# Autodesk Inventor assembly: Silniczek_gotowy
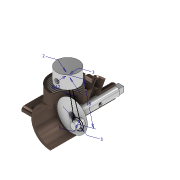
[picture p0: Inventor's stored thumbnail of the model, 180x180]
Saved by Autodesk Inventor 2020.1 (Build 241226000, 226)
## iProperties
Manager: www.cadconsulting.pl
Company: Fabian Stasiak CAD Consulting
Created: 2019-06
Part Number: Silniczek_gotowy
Document SubType Name: Assembly
Designer: F.Stasiak
Author: F.Stasiak
Subject: Zbiór ćwiczeń. Autodesk Inventor 2020. Kurs podstawowy
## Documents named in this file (5)
- C:\2020_Kurs_podstawowy\R6 Zespoły\Wiązania\Silniczek\Silniczek_gotowy.iam
- C:\2020_Kurs_podstawowy\R6 Zespoły\Wiązania\Silniczek\Korpus_234.ipt
- C:\2020_Kurs_podstawowy\R6 Zespoły\Wiązania\Silniczek\Wałek_234.ipt
- C:\2020_Kurs_podstawowy\R6 Zespoły\Wiązania\Silniczek\Tłok_234.ipt
- C:\2020_Kurs_podstawowy\R6 Zespoły\Wiązania\Silniczek\Korbowód_1.ipt
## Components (4 placed, 4 different names)
1. Korpus_234:1 — Wstawiające:1, Kątowe:1, Zestawiające:1
2. Wałek_234:1 — Wstawiające:1, Kątowe:1, Równoległe:1, Zestawiające:2
3. Tłok_234:1 — Zestawiające:1, Zestawiające:3
4. Korbowód_1:1 — Zestawiające:2, Zestawiające:3
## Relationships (6: Mate 3, Insert 1, Angle 1, Flush 1)
- Wstawiające:1 [Insert]: Korpus_234:1 ↔ Wałek_234:1
- Kątowe:1 [Angle]: Korpus_234:1 ↔ Wałek_234:1
- Zestawiające:1 [Mate]: Korpus_234:1 ↔ Tłok_234:1
- Równoległe:1 [Flush]: Wałek_234:1
- Zestawiające:2 [Mate]: Wałek_234:1 ↔ Korbowód_1:1
- Zestawiające:3 [Mate]: Tłok_234:1 ↔ Korbowód_1:1
